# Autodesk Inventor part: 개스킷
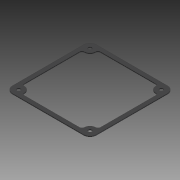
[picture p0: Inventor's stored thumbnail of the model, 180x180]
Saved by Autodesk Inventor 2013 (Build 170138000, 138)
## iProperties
Created: 2019-04
Part Number: 개스킷
Material: 고무
Document SubType Name: Modeling
Designer: mduedu
Density: 0.93 g/cm^3
Mass: 2.09699 g
Surface Area: 53.3016 cm^2
Volume: 2.25483 cm^3
Author: mduedu
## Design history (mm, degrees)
sketch "스케치1"
  geometry: L1 (52.5, 52.5)-(-52.5, 52.5); L2 (-52.5, 52.5)-(-52.5, -52.5); L3 (-52.5, -52.5)-(52.5, -52.5); L4 (52.5, -52.5)-(52.5, 52.5); L5 (52.5, 52.5)-(-52.5, -52.5); L6 (-52.5, 52.5)-(52.5, -52.5); 1 further point
  constraints: 12 end point, 2 midpoint, 2 parallel, 1 horizontal, 1 perpendicular
  dimensions: "d0" = 105 distance of L3.end L2.end; "d1" = 105 distance of L2.end L1.end
extrude "돌출1" new body sketch "스케치1" distance "d2" = 1; taper "d3" = 0 deg
sketch "스케치2"
  geometry: L1 (-52.5, -52.5)-(52.5, -52.5) reference; L2 (52.5, -52.5)-(52.5, 52.5) reference; L3 (52.5, 52.5)-(-52.5, 52.5) reference; L4 (-52.5, 52.5)-(-52.5, -52.5) reference; L5 (-47.5, 47.5)-(47.5, 47.5); L6 (47.5, 47.5)-(47.5, -47.5); L7 (47.5, -47.5)-(-47.5, -47.5); L8 (-47.5, -47.5)-(-47.5, 47.5); 1 further point
  constraints: 8 end point, 3 other
  dimensions: "d4" = 5 distance between parallel lines of L5 L3
extrude "돌출2" cut sketch "스케치2" stored distance "d5" = 1; taper "d6" = 0 deg
fillet "모깎기1" dims "d7" = 8
sketch "스케치3"
  geometry: C1 r 7 at (-44.5, 44.5); C2 r 7 at (-44.5, -44.5); C3 r 7 at (44.5, -44.5); C4 r 7 at (44.5, 44.5); A1 r 8 centre (-44.5, 44.5) between (-44.5, 52.5) and (-52.5, 44.5) reference; A2 r 8 centre (-44.5, -44.5) between (-52.5, -44.5) and (-44.5, -52.5) reference; A3 r 8 centre (44.5, -44.5) between (44.5, -52.5) and (52.5, -44.5) reference; A4 r 8 centre (44.5, 44.5) between (52.5, 44.5) and (44.5, 52.5) reference; 1 further point
  constraints: 4 centre point, 4 coincident, 3 equal radius
  dimensions: "d18" = 14 diameter of C1
extrude "돌출3" join sketch "스케치3" stored distance "d8" = 1; taper "d9" = 0 deg
fillet "모깎기2" dims "d10" = 3
sketch "스케치4"
  geometry: A1 r 8 centre (-44.5, 44.5) between (-44.5, 52.5) and (-52.5, 44.5) reference; A2 r 8 centre (44.5, 44.5) between (52.5, 44.5) and (44.5, 52.5) reference; A3 r 8 centre (44.5, -44.5) between (44.5, -52.5) and (52.5, -44.5) reference; A4 r 8 centre (-44.5, -44.5) between (-52.5, -44.5) and (-44.5, -52.5) reference; 5 further points
  constraints: 4 coincident
hole "구멍1" sketch "스케치4" at (-44.5, 44.5), (44.5, 44.5), (44.5, -44.5), (-44.5, -44.5) diameter "d11" = 4.5; stored, may be unused: countersink angle "d15" = 90 deg, drill point angle "d17" = 118 deg; dims "d12" = 6, "d13" = 4, "d14" = 2, "d16" = 8
node "솔리드1"
node "투영된 루프1"
